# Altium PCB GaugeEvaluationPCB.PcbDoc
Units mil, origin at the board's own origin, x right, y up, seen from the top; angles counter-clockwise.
Board outline 3520.03 x 1613.16 mil, 2 copper layers (Top Layer, Bottom Layer), stack 62 mil thick; 46 components, 37 nets, 143 pads, 56 vias.
Unrouted connection lines stored in the file: 25.
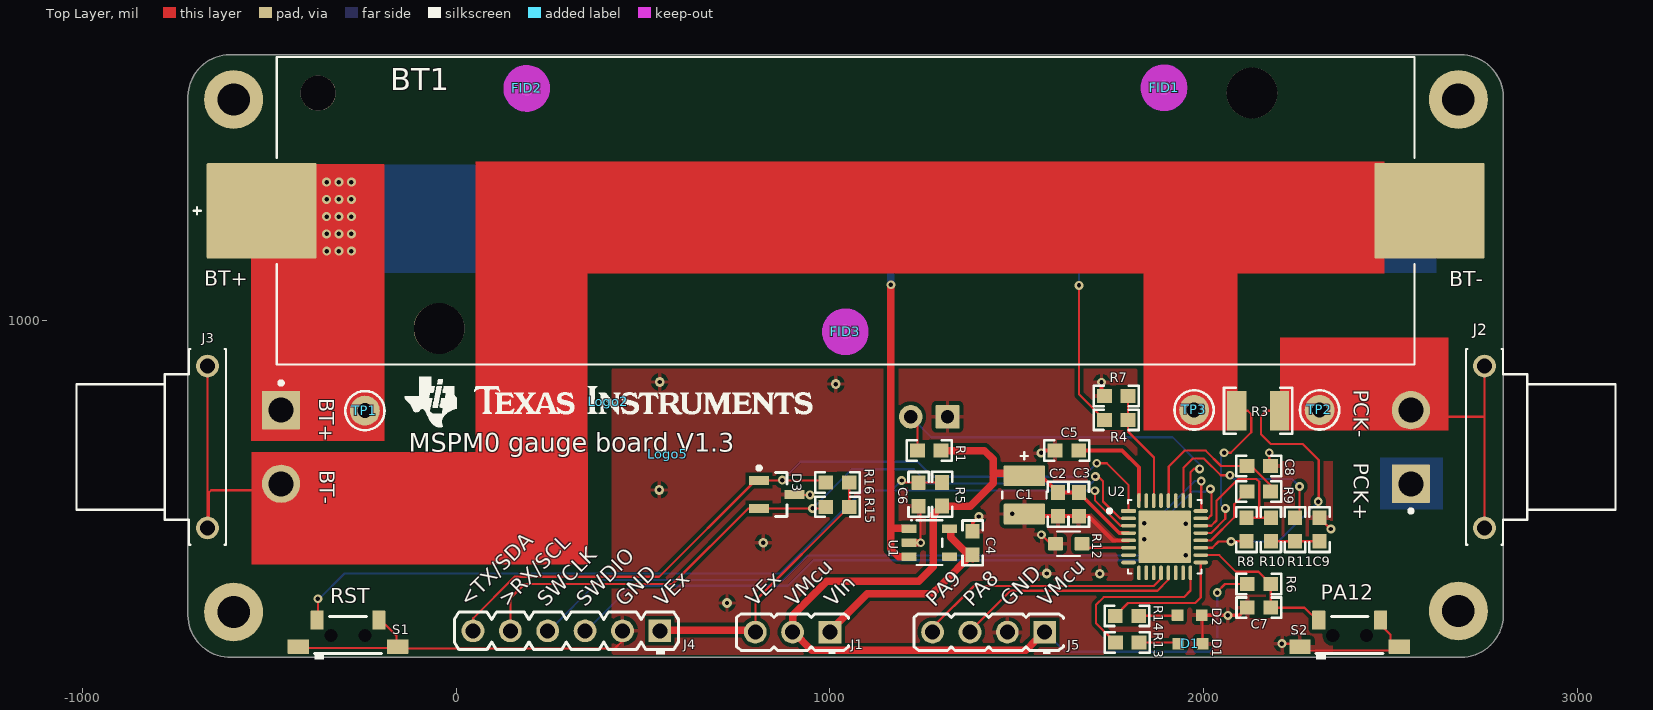
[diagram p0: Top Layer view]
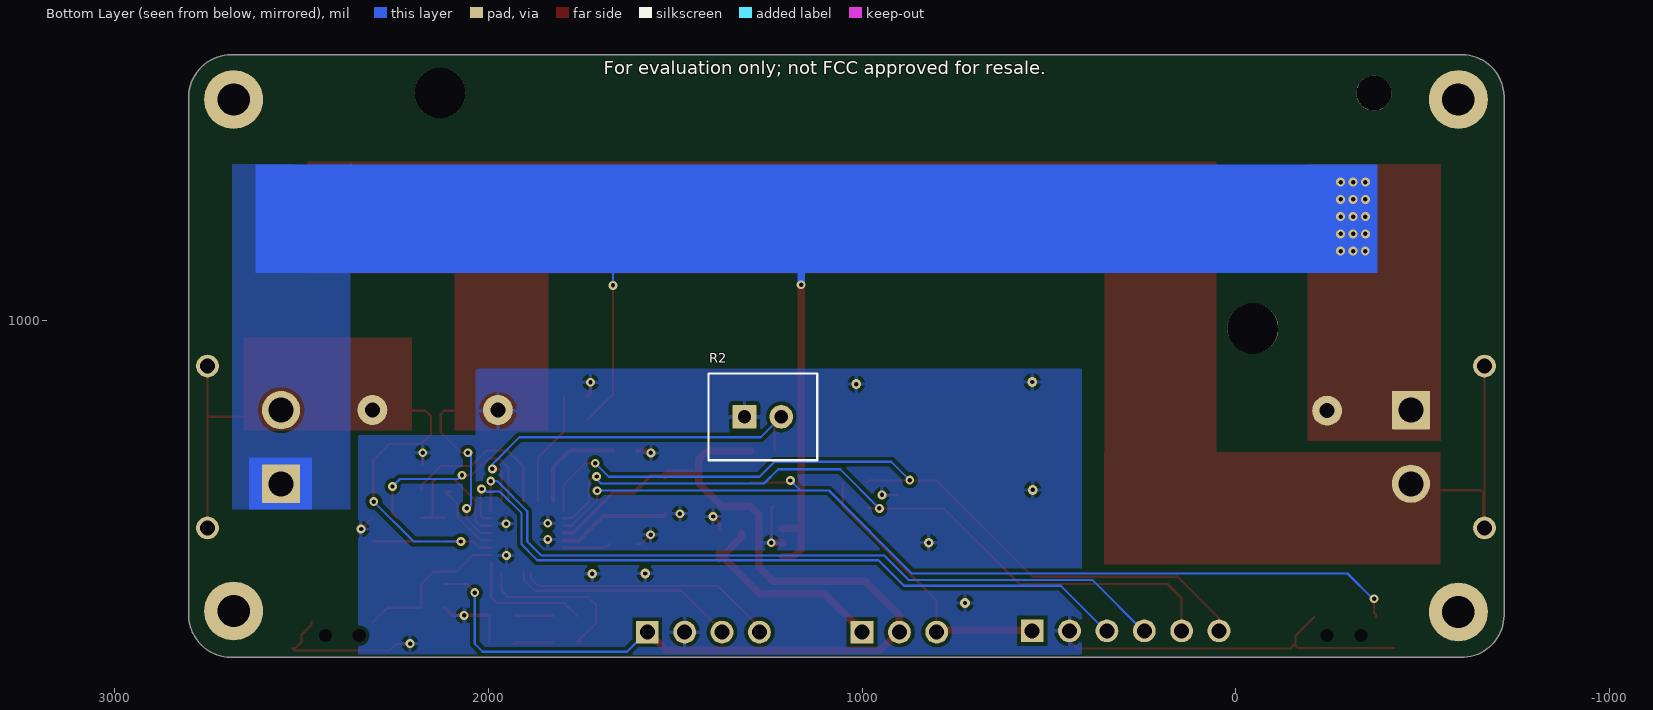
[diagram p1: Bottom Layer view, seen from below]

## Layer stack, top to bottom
Top Solder: solder mask 0.4, Solder Resist, Dk 3.5
Top Layer: signal copper 1.4
Dielectric1: core 59.2, FR-4, Dk 4.8
Bottom Layer: signal copper 1.4
Bottom Solder: solder mask 0.4, Solder Resist, Dk 3.5

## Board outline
-601.61,99.61 cw(c-603.45,213.91) -717.76,212.44 cw(c-712.75,212.5) -717.77,212.5 -717.77,1599.75 cw(c-712.75,1599.75) -717.63,1600.9 cw(c-603.34,1598.45) -604.81,1712.76 cw(c-604.75,1707.75) -602.57,1712.26 2686.19,1712.26 cw(c2686.19,1707.25) 2687.23,1712.16 cw(c2687.95,1597.84) 2802.26,1599.31 cw(c2797.25,1599.25) 2802.27,1599.25 cw(c2797.25,1599.25) 2802.26,1599.22 2802.27,212.25 cw(c2797.25,212.25) 2802.12,211.05 cw(c2687.84,214.05) 2689.31,99.74 cw(c2689.25,104.75) 2689.25,99.73 -600.56,99.73 cw(c-601.69,104.62)

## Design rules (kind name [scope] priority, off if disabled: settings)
AcuteAngle [All] p1: minimum=4.50000000000000E+0001 checktracksonly=FALSE
AssemblyTestPointUsage [All] p1: valid=2
BoardOutlineClearance BoardOutlineClearance_MountingHoles [OnCopper and InComponentClass('Mounting Holes')] p1: gap=6 ignorepadtopadclearanceinfootprint=FALSE
BoardOutlineClearance BoardOutlineClearance_Poly [OnCopper and IsPoly] p2: gap=6 ignorepadtopadclearanceinfootprint=FALSE
BoardOutlineClearance [OnCopper and Not InComponentClass('Logo') and not InComponentClass('FiducialMark') and not InRegion(1000,500,4000,800) and not InPoly] p3: gap=6 ignorepadtopadclearanceinfootprint=FALSE
Clearance Clearance_Keepouts [((IsTrack Or IsArc) And Not InPoly) And IsFree and IsKeepOut vs ((IsTrack Or IsArc) And Not InPoly) And IsFree and IsKeepOut] p1: gap=10 ignorepadtopadclearanceinfootprint=FALSE
Clearance Clearance_Poly [InPolygon] p2: gap=10 ignorepadtopadclearanceinfootprint=TRUE
Clearance Clearance_FiducialMark [IsKeepOut and InComponentClass('FiducialMark') vs IsPad and InComponentClass('FiducialMark')] p3: gap=10 ignorepadtopadclearanceinfootprint=FALSE
Clearance [All] p4: gap=6 ignorepadtopadclearanceinfootprint=TRUE
ComponentClearance ComponentClearance_MountingHoles_FiducialMarks [InComponentClass('Mounting Holes') vs InComponentClass('FiducialMark')] p1: gap=0 collisioncheckmode=3 verticalgap=10 showdistances=FALSE
ComponentClearance ComponentClearance_Shunt [InComponentClass('Header') vs InComponentClass('Shunt')] p2: gap=0 collisioncheckmode=3 verticalgap=0 showdistances=FALSE
ComponentClearance ComponentClearance_Logo [InComponentClass('Logo')] p3: gap=0 collisioncheckmode=3 verticalgap=10 showdistances=FALSE
ComponentClearance ComponentClearance_ScrewToNut [(HasFootprint('NY PMS 440 0025 PH')) vs (HasFootprint('Keystone_1902C'))] p4: gap=0 collisioncheckmode=3 verticalgap=10 showdistances=FALSE
ComponentClearance ComponentClearance_MountingHoles [InComponentClass('Mounting Holes')] p5: gap=0 collisioncheckmode=3 verticalgap=100000 showdistances=FALSE
ComponentClearance ComponentClearance_SmallPassives [HasFootprint('0201*') or HasFootprint('0402*') or HasFootprint('0508') or HasFootprint('0603*') or HasFootprint('0612') or HasFootprint('0805*') or HasFootprint('0815*') or HasFootprint('0830*') or HasFootprint('1206*') or HasFootprint('1210*') or HasFootprint('1808*') or HasFootprint('1812*') or HasFootprint('1825*') or HasFootprint('2010*') or HasFootprint('2220*') or HasFootprint('2225*') or HasFootprint('2512*') or HasFootprint('2728*') or HasFootprint('3518*') vs HasFootprint('0201*') or HasFootprint('0402*') or HasFootprint('0508') or HasFootprint('0603*') or HasFootprint('0612') or HasFootprint('0805*') or HasFootprint('0815*') or HasFootprint('0830*') or HasFootprint('1206*') or HasFootprint('1210*') or HasFootprint('1808*') or HasFootprint('1812*') or HasFootprint('1825*') or HasFootprint('2010*') or HasFootprint('2220*') or HasFootprint('2225*') or HasFootprint('2512*') or HasFootprint('2728*') or HasFootprint('3518*')] p6: gap=0 collisioncheckmode=3 verticalgap=10 showdistances=FALSE
ComponentClearance ComponentClearance_THtoSMT [IsThruComponent vs IsSMTComponent] p7: gap=0 collisioncheckmode=3 verticalgap=30 showdistances=FALSE
ComponentClearance ComponentClearance_THtoTH [IsThruComponent vs IsThruComponent] p8: gap=0 collisioncheckmode=3 verticalgap=30 showdistances=FALSE
ComponentClearance [All] p9: gap=0 collisioncheckmode=3 verticalgap=10 showdistances=FALSE
DiffPairsRouting [All] p1: maxlimit=100 minlimit=10 mostfreqgap=10 toplayer_minwidth=15 toplayer_maxwidth=15 toplayer_prefwidth=15 bottomlayer_minwidth=15 bottomlayer_maxwidth=15 bottomlayer_prefwidth=15 maxuncoupledlength=1000
FabricationTestPointUsage TestPointUsage [All] p1: valid=2 allowmultiple=FALSE
FabricationTestpoint Testpoint [All] p1: side=3 testpointundercomponent=TRUE minsize=40 maxsize=100 preferedsize=60 minholesize=0 maxholesize=40 preferedholesize=32 testpointgrid=1 allowsidetop=TRUE allowsidebottom=TRUE usegrid=TRUE gridtolerance=0.01
FanoutControl Fanout_LCC [IsLCC] p1: bgadir=Out bgaviamode=Centered fanoutstyle=Auto fanoutdirection=Alternating viagrid=1 // Fanout_LCC (Default Rule)
FanoutControl Fanout_BGA [IsBGA] p2: bgadir=Out bgaviamode=Centered fanoutstyle=Auto fanoutdirection=Alternating viagrid=1 // Fanout_BGA (Default Rule)
FanoutControl Fanout_Default [All] p4: bgadir=Out bgaviamode=Centered fanoutstyle=Auto fanoutdirection=Alternating viagrid=1 // Fanout_Default (Default Rule)
FanoutControl Fanout_Small [(CompPinCount < 5)] p5: bgadir=Out bgaviamode=Centered fanoutstyle=Auto fanoutdirection=OutThenIn viagrid=1 // Fanout_Small (Default Rule)
Height [All] p1: minheight=0 maxheight=99999 prefheight=500
HoleSize [All] p1: absolutevalues=TRUE maxlimit=251 minlimit=7.87 maxpercent=80.000 minpercent=20.000
MinimumAnnularRing MinimumAnnularRing_ThermalPadVias [IsVia and InAnyComponent] p1: minimumring=5.91
MinimumAnnularRing [All] p2: minimumring=5.91
MinimumSolderMaskSliver MinimumSolderMaskSliver_Logo [InComponentClass('Logo') vs InComponentClass('Logo')] p1: minsoldermaskwidth=0.7
MinimumSolderMaskSliver [All] p2: minsoldermaskwidth=0
PlaneConnect [All] p1: planeconnectstyle=Relief reliefexpansion=10 reliefentries=4 reliefconductorwidth=10 reliefairgap=10
PolygonConnect [All] p1: connectstyle=Relief reliefconductorwidth=10 reliefentries=4 polygonreliefangle="90 Angle" airgapwidth=10
RoutingVias ThermalPadVias [IsVia and InAnyComponent] p1: holewidth=11.81 width=23.62 viastyle="Through Hole" minholewidth=7.87 minwidth=19.68 maxholewidth=17.72 maxwidth=35.43
RoutingVias [All] p2: holewidth=11.81 width=23.62 viastyle="Through Hole" minholewidth=7.87 minwidth=23.62 maxholewidth=40 maxwidth=65
SilkToBoardRegionClearance [Not ((IsComment or IsDesignator) And (Hide <> 'False')) and not InRegion(1000,500,4000,800)] p1:
SilkToSilkClearance SilkToSilkClearance_Pb-FreeLogo [(HasFootprint('Pb-Free_Overlay_Medium') OR HasFootprint('Pb-Free_Overlay_Small')) vs (HasFootprint('Pb-Free_Overlay_Medium') OR HasFootprint('Pb-Free_Overlay_Small'))] p1: silktosilkclearance=0
SilkToSilkClearance [All] p2: silktosilkclearance=0
SilkToSolderMaskClearance SilkToComponentPadClearance [(IsPad or IsFill or IsRegion) and InAnycomponent] p1: minsilkscreentomaskgap=0 clearancetoexposedcopper=TRUE
SilkToSolderMaskClearance "Silk to Solder Mask Opening" [All] p2: minsilkscreentomaskgap=0 clearancetoexposedcopper=FALSE
SolderMaskExpansion [All] p1: expansion=1.97 istentingtop=FALSE
UnRoutedNet [All] p1: checkbadconnections=TRUE
Width [All] p1: maxlimit=100 minlimit=6 preferedwidth=6 checkconnectedcopper=TRUE
13 further rules are at their usual default settings.

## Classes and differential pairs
component class Logo: Logo2
component class FiducialMark: FID1 FID2 FID3
component class Header: J1 J4 J5

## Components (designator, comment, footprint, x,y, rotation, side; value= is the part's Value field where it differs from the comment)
BT1 "1042P" FP-1042P_BT_HOLDER-MFG 1042.25,1294.75 r180 top
C1 "TAJB475K010RNJ" FP-TAJB475K010RNJ_1210-MFG 1520.5,534.5 r90 top
C2 "GRM188R61A106KAALD" 0603 1610.5,509.25 r90 top value=10uF
C3 "C0603X104K3RACTU" 0603 1666.25,509.25 r270 top value=0.1uF
C4 "C1608X5R1A105K080AC" 0603 1382.25,406 r90 top value=1uF
C5 "C0603C474K8PACTU" 0603 1634.25,653.5 r180 top value=0.47uF
C6 "C0603X104K3RACTU" 0603 1237.73,535.88 r270 top value=0.1uF
C7 "C0603X104K3RACTU" 0603 2148.25,232.75 r180 top value=0.1uF
C8 "C0603X104K3RACTU" 0603 2147.75,611.75 r0 top value=0.1uF
C9 "C0603X104K3RACTU" 0603 2310,441.75 r90 top value=0.1uF
D1 "SML-D12U1WT86" LED_SMLD12_RED 1964.98,136.03 r0 top value=Red
D2 "SML-D12U1WT86" LED_SMLD12_RED 1963,212.78 r0 top value=Green
D3 "BAT64-06" INF-SOT23_M 858,535.75 r0 top
FID1 "Fiducial" Fiducial10-30 1894.25,1623.75 r0 top
FID2 "Fiducial" Fiducial10-30 189.03,1622.25 r90 top
FID3 "Fiducial" Fiducial10-30 1041.5,971 r90 top
J1 "22284033" Molex_0022284033 900.5,167.25 r180 top
J2 "XT30PW-F" FP-XT30PW-F_CONN_SOCKET_DC2-MFG 2902.34,662.71 r270 top
J3 "XT30PW-F" FP-XT30PW-F_CONN_SOCKET_DC2-MFG -815.75,662.71 r90 top
J4 "PBC06SAAN" Sullins_PxC06SAAN 295.16,170.75 r180 top
J5 "22284043" Molex_0022284043 1425,167.25 r180 top
Logo2 "Texas Instruments" TI_Horizontal_Overlay_Small 407.66,784.12 r0 top
Logo5 "FCC disclaimer" FCC_disclaimer 566.5,643.25 r0 top
R1 "RNCF0603TKY10K0" 0603 1266.25,653.25 r0 top value=10.0k
R2 "NTCALUG01A103F161L" FP-NTCALUG01A103F161L_PTH_7MM2_5MM6-MFG 1265.79,743.5 r180 bottom value=10k
R3 "ERJ-L14KF20MU" 1210 2146.09,760 r180 top value=0.02
R4 "RG1608P-223-B-T5" 0603 1766.25,735.54 r180 top value=220.0k
R5 "RT0603BRD0747KL" 0603 1300.48,536.13 r270 top value=47.0k
R6 "RT0603BRD0747KL" 0603 2148.25,296 r180 top value=47.0k
R7 "RG1608P-104-B-T5" 0603 1766.25,799.18 r0 top value=100.0k
R8 "ERJ3EKF1602V" 0603 2115,441.75 r270 top value=16.0k
R9 "RG1608P-162-B-T5" 0603 2147.75,543.5 r0 top value=1.60k
R10 "RC0603FR-07115KL" 0603 2180.04,441.75 r90 top value=110k
R11 "RG1608P-162-B-T5" 0603 2245.02,441.75 r90 top value=1.60k
R12 "RN73C1J100KBTG" FP-RN73C1J100KBTG_0603-MFG 1639.25,403.75 r180 top value=100k
R13 "RC0603FR-071KL" 0603 1796,139.28 r0 top value=1.00k
R14 "RC0603FR-071KL" 0603 1795.25,211.03 r0 top value=1.00k
R15 "RC0603FR-072K2L" 0603 1020.59,502.75 r0 top value=2.20k
R16 "RC0603FR-072K2L" 0603 1020.59,567.5 r0 top value=2.20k
S1 "1188E-1K2-V-TR" SW_1188E -289.25,171.75 r90 top
S2 "1188E-1K2-V-TR" SW_1188E 2391.03,171.75 r90 top
TP1 "5117" Keystone5117 -243.97,759.88 r90 top
TP2 "5117" Keystone5117 2310.5,761.75 r90 top
TP3 "5117" Keystone5117 1974.75,761.75 r90 top
U1 "TLV70018DDCR" DDC0005A_N 1266.12,406.6 r0 top
U2 "MSPM0L1306TRHB" RHB0032E-IPC_A 1896.03,422.58 r0 top

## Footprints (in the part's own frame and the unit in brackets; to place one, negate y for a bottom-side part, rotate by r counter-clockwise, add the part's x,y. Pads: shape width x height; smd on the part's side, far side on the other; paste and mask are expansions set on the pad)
0603 [mm] "0603 from SM-752 data"
  rect 1x0.95 smd: 1(-0.8,0) 2(0.8,0)
  silkscreen extent -1.52,-0.69 1.52,0.69, body extent -0.87,-0.47 0.87,0.47, height 1
1210 [mm] "1210 from SM-752 data"
  rect 1.3x2.7 smd: 1(-1.45,0) 2(1.45,0)
  silkscreen extent -2.32,-1.57 2.32,1.57, body extent -1.7,-1.35 1.7,1.35, height 1.35
DDC0005A_N [mm]
  rrect17% 1x0.6 smd: 1(-1.375,0.95) 2(-1.375,0) 3(-1.375,-0.95) 4(1.375,-0.95) 5(1.375,0.95)
  silkscreen extent -1.25,-1.52 0.88,1.57, body extent -1.41,-1.45 1.41,1.45, height 1.1
FCC_disclaimer [mil]
Fiducial10-30 [mm]
  round 1 smd mask+1: 1(0,0)
  Top Layer keep-out circle w1.678: c0,0 r0.75
FP-1042P_BT_HOLDER-MFG [mil]
  rrect2% 294x255 smd paste+0 mask+0: 1(-1562.5,0) 2(1562.5,0)
  round 135.83 hole 135.83 unplated paste-39370.1 mask+0: ""(-1087.5,-315) ""(1087.5,315)
  round 94 hole 94 unplated paste-39370.1 mask+0: ""(1411.5,-315)
  silkscreen extent -1522,-412 1745,412, body extent -1713,-415 1713,415, height 10
FP-NTCALUG01A103F161L_PTH_7MM2_5MM6-MFG [mm]
  rrect6% 1.61x1.61 hole 0.91 paste-1000 mask+0: 1(-1.25,0)
  round 1.61 hole 0.91 paste-1000 mask+0: 2(1.25,0)
  silkscreen extent -3.7,-2.95 3.7,2.95, body extent -3.6,-2.82 3.6,2.8, height 54
FP-RN73C1J100KBTG_0603-MFG [mm]
  rrect11% 1x0.9 smd paste+0 mask+0: 1(-0.9,0) 2(0.9,0)
  silkscreen extent -0.77,-0.82 0.78,0.83, body extent -0.77,-0.4 0.78,0.4, height 0.55
FP-TAJB475K010RNJ_1210-MFG [mm]
  rrect7% 1.4x2.8 smd paste+0 mask+0: 1(-1.3,0) 2(1.3,0)
  silkscreen extent -0.23,-1.5 2.9,1.5, body extent -2.1,-1.6 2.1,1.6, height 0.25
FP-XT30PW-F_CONN_SOCKET_DC2-MFG [mm]
  rrect4% 2.6x2.6 hole 1.7 paste-1000 mask+0: 1(2.5,-8.825)
  round 2.6 hole 1.7 paste-1000 mask+0: 2(-2.5,-8.825)
  round 1.55 hole 1 paste-1000 mask+0: 3(-5.5,-3.825) 4(5.5,-3.825)
  silkscreen extent -6.65,-8.95 6.65,5.07, body extent -6.75,-10.23 6.75,5.18, height 0.25
INF-SOT23_M [mm] "SOT23, 3-Leads, Body 2.9x1.3 mm, Pitch 0.95 mm, IPC Low Density"
  rect 1.35x0.6 smd: 1(-1.2,0.95) 2(-1.2,-0.95) 3(1.2,0)
  silkscreen extent -1.32,-1.5 0.7,1.92, body extent -0.7,-1.5 0.7,1.5, height 1.1
Keystone5117 [mil] "For Keystone 500x miniature loop terminals"
  round 80 hole 40: 1(0,0)
  silkscreen extent -52,-52 52,52, body extent -49,-49 49,49, height 182
LED_SMLD12_RED [mm] "SMD, 2-Leads, Body 1.6x0.8mm"
  rrect12% 0.8x0.8 smd: 1(-0.825,0) 2(0.825,0)
  body extent -0.8,-0.4 0.8,0.4, height 0.55
Molex_0022284033 [mm] "Header, 2.54mm, 3x1, TH"
  rect 1.55x1.55 hole 1.02: 1(-2.54,0)
  round 1.55 hole 1.02: 2(0,0) 3(2.54,0)
  silkscreen extent -3.81,-1.24 3.81,1.5, body extent -3.81,-1.24 3.81,1.24, height 8.4
Molex_0022284043 [mm] "Header, 2.54mm, 4x1, TH"
  rect 1.55x1.55 hole 1.02: 1(-3.81,0)
  round 1.55 hole 1.02: 2(-1.27,0) 3(1.27,0) 4(3.81,0)
  silkscreen extent -5.08,-1.24 5.08,1.5, body extent -5.08,-1.24 5.08,1.24, height 8.4
RHB0032E-IPC_A [mm]
  rrect41% 1.01x0.242 smd paste+0 mask+0: 1(-2.451,1.75)
  rrect100% 1.01x0.242 smd paste+0 mask+0: 2(-2.451,1.25) 3(-2.451,0.75) 4(-2.451,0.25) 5(-2.451,-0.25) 6(-2.451,-0.75) 7(-2.451,-1.25) 8(-2.451,-1.75) 17(2.451,-1.75) 18(2.451,-1.25) 19(2.451,-0.75) 20(2.451,-0.25) 21(2.451,0.25) 22(2.451,0.75) 23(2.451,1.25) 24(2.451,1.75)
  rrect100% 0.242x1.01 smd paste+0 mask+0: 9(-1.75,-2.451) 10(-1.25,-2.451) 11(-0.75,-2.451) 12(-0.25,-2.451) 13(0.25,-2.451) 14(0.75,-2.451) 15(1.25,-2.451) 16(1.75,-2.451) 25(1.75,2.451) 26(1.25,2.451) 27(0.75,2.451) 28(0.25,2.451) 29(-0.25,2.451) 30(-0.75,2.451) 31(-1.25,2.451) 32(-1.75,2.451)
  rrect3% 3.55x3.55 smd paste-1000 mask+0: 33(0,0)
  silkscreen extent -3.88,-2.5 2.5,2.5, body extent -3.46,-3.46 3.46,3.46, height 0.25
Sullins_PxC06SAAN [mm] "Header, 2.54mm, 6x1, TH"
  rect 1.55x1.55 hole 1.016: 1(-6.35,0)
  round 1.55 hole 1.016: 2(-3.81,0) 3(-1.27,0) 4(1.27,0) 5(3.81,0) 6(6.35,0)
  silkscreen extent -7.62,-1.27 7.62,1.6, body extent -7.62,-1.27 7.62,1.27, height 8.38
SW_1188E [mm] "SMD, 4-Leads, Body 7.8x3.5mm"
  rrect10% 1x1.45 smd: 1(-1.1,3.375) 2(-1.1,-3.375)
  rrect11% 1.3x0.9 smd: 3(0.7,2.1) 4(0.7,-2.1)
  round 0 hole 0.9 unplated: ""(-0.35,1.15) ""(-0.35,-1.15)
  silkscreen extent -1.97,-2.28 0.95,2.28, body extent -2.55,-3.9 1.05,3.9, height 3.5
TI_Horizontal_Overlay_Small [mil]
  silkscreen extent -545,-68 545,67

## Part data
BT1: library part CMP-0092114-1, "Battery Holder (Open) 18650 1 Cell SMD (SMT) Tab", Digikey Part Number=36-1042P-ND, Manufacturer=Keystone, Mouser Part Number=534-1042P, Operating Temperature Range="-50°C to +145°C"
C1: library part CMP-0089269-1, "220µF Molded Tantalum Capacitors 10V 1411 (3528 Metric), 1210 4Ohm", Digikey Part Number=478-3886-1-ND, Manufacturer="AVX Corporation", Mouser Part Number=581-TAJB475K010R, Operating Temperature Range="-55°C to +125°C", Tolerance_%=10%, ValueDisplayed=220uF
C2: library part CMP-0086193-1, "CAP, CERM, 10 µF, 10 V,+/- 10%, X5R, 0603", Cap_Case=0603, Manufacturer=MuRata, TempCo=X5R, Tolerance_%=10%, Value2=10V, ValueDisplayed=10µF
C3 C6 C7 C8 C9: library part CMP-0006979-3, "CAP, CERM, 0.1 uF, 25 V, +/- 10%, X7R, 0603", Cap_Case=0603, Manufacturer=Kemet, Supplier Part Number 1=399-5345-1-ND, TempCo=X7R, Tolerance_%=10%, Value1=Unknown, Value2=25V, ValueDisplayed=0.1uF
C4: library part CMP-0007002-5, "CAP, CERM, 1 uF, 10 V, +/- 10%, X5R, 0603", Cap_Case=0603, Manufacturer=TDK, Supplier Part Number 1=445-1321-1-ND, TempCo=X5R, Tolerance_%=10%, Value1=Unknown, Value2=10V, ValueDisplayed=1uF
C5: library part CMP-0006945-1, "CAP, CERM, 0.47 uF, 10 V, +/- 10%, X5R, 0603", Cap_Case=0603, Manufacturer=Kemet, Supplier Part Number 1=399-3114-1-ND, TempCo=X5R, Tolerance_%=10%, Value1=Unknown, Value2=10V, ValueDisplayed=0.47uF
D1 D2: library part CMP-0086209-1, "LED, Red, SMD", Color=Red, Manufacturer=Rohm, Power_TotalModule=54mW, Value1=0.054W, Value2=2.2V
D3: library part CMP-1182-00011-1, "Silicon Schottky Diode, SOT23, Reel, Green", Manufacturer=Infineon
FID1 FID2 FID3: library part CMP-0077181-1, "Fiducial mark.  There is nothing to buy or mount.", Manufacturer=N/A
J1: library part CMP-0055332-1, "Header, 2.54mm, 3x1, Tin, TH", Color=Black, Current_A=4A, Manufacturer=Molex, Supplier Part Number 1=WM50016-03-ND, Voltage_V=250V
J2 J3: library part CMP-0035193-1, "Socket, DC supply, XT30, female, PIN: 2, on PCBs, THT, yellow, 15A", Current_A=15A, Manufacturer=Amass, Operating Temperature Range="-20°C to +120°C", Voltage_V=500V
J4: library part CMP-0054603-1, "Header, 2.54mm, 6x1, Gold, TH", Color=Black, Current_A=3A, Manufacturer="Sullins Connector Solutions", Supplier Part Number 1=S1011E-06-ND
J5: library part CMP-0055331-1, "Header, 2.54mm, 4x1, Tin, TH", Color=Black, Current_A=4A, Manufacturer=Molex, Supplier Part Number 1=WM50016-04-ND, Voltage_V=250V
Logo2: library part CMP-0074838-1, "Texas Instrument Corporate Signature"
Logo5: library part CMP-0074847-1, "FCC_disclaimer"
R1: library part CMP-0023626-3, "RES, 10.0 k, 1%, 0.063 W, 0603", Manufacturer="Stackpole Electronics Inc", Power_W=63mW, Supplier Part Number 1=RNCF0603TKY10K0CT-ND, TempCo="5 ppm/C", Tolerance_%=1%, Value1=0.01%, Value2=0.063W, Value_Code=10k0
R2: library part CMP-0091769-1, "NTC Thermistors; NTC Lug 10k 1% 3435K awg#24 PTFE 600V 16", B Tolerance=1%, Digikey Part Number=BC2896-ND, Manufacturer=Vishay, Mouser Part Number=594-NTLUG01A103F161L, Operating Temperature Range="-40°C to +150°C"
R3: library part CMP-0015069-2, "RES, 0.02, 1%, 0.33 W, 1210", Manufacturer=Panasonic, Power_W=330mW, Supplier Part Number 1=P20NACT-ND, TempCo="300 ppm/C", Tolerance_%=1%, Value2=0.33W, Value_Code=R020, ValueDisplayed=0.02
R4: library part CMP-0023474-2, "RES, 220.0 k, 0.1%, 0.1 W, 0603", Manufacturer="Susumu Co Ltd", PartNumber=RG1608P-224-B-T5, Power_W=100mW, Supplier Part Number 1=RG16P220.0KBCT-ND, TempCo="25 ppm/C", Tolerance_%=0.1%, Value2=0.1W, Value_Code=220k0, ValueDisplayed=220.0k
R5: library part CMP-0024267-2, "RES, 47.0 k, 1%, 0.1 W, 0603", Manufacturer="Yageo America", Power_W=100mW, TempCo="25 ppm/C", Tolerance_%=1%, Value1=0.1%, Value2=0.1W, Value_Code=47k0, ValueDisplayed=47.0k
R6: library part CMP-0024267-2, "RES, 47.0 k, 1%, 0.1 W, 0603", Manufacturer="Yageo America", Power_W=100mW, TempCo="25 ppm/C", Tolerance_%=0.1%, Value1=1%, Value2=0.1W, Value_Code=47k0, ValueDisplayed=47.0k
R7: library part CMP-0023404-1, "RES, 100.0 k, 0.1%, 0.1 W, 0603", Manufacturer="Susumu Co Ltd", Power_W=100mW, Supplier Part Number 1=RG16P10.0KBCT-ND, TempCo="25 ppm/C", Tolerance_%=0.1%, Value2=0.1W, Value_Code=100k0, ValueDisplayed=100.0k
R8: library part CMP-0078661-1, "RES, 16.0 k, 1%, 0.1 W, AEC-Q200 Grade 0, 0603", Manufacturer=Panasonic, Power_W=100mW, Supplier Part Number 1=P16.0KHCT-ND, TempCo="100 ppm/C", Tolerance_%=1%, Value2=0.1W, Value_Code=16k0, ValueDisplayed=16.0k
R9 R11: library part CMP-0023448-3, "RES, 1.60 k, 0.1%, 0.1 W, 0603", Manufacturer="Susumu Co Ltd", Power_W=100mW, Supplier Part Number 1=RG16P1.6KBCT-ND, TempCo="25 ppm/C", Tolerance_%=0.1%, Value2=0.1W, Value_Code=1k60, ValueDisplayed=1.60k
R10: library part CMP-0022756-4, "RES, 110 k, 1%, 0.1 W, 0603", Manufacturer=Yageo, Power_W=100mW, Supplier Part Number 1=311-110KHRCT-ND, TempCo="100 ppm/C", Tolerance_%=1%, Value2=0.1W, Value_Code=110k
R12: library part CMP-0093027-1, "Thin Film Resistors RN 0603 100KΩ 0.1% 10ppm/°C", Manufacturer="TE Connectivity", Operating Temperature Range="-55°C to +155°C", Power_W=63mW, TempCo=10ppm/°C, Tolerance_%=0.1%
R13 R14: library part CMP-0022895-5, "RES, 1.00 k, 1%, 0.1 W, 0603", Manufacturer=Yageo, Power_W=100mW, Supplier Part Number 1=311-1.00KHRCT-ND, TempCo="100 ppm/C", Tolerance_%=1%, Value2=0.1W, Value_Code=1k00, ValueDisplayed=1.00k
R15 R16: library part CMP-0022986-5, "RES, 2.20 k, 1%, 0.1 W, 0603", Manufacturer=Yageo, Power_W=100mW, Supplier Part Number 1=311-2.20KHRCT-ND, TempCo="100 ppm/C", Tolerance_%=1%, Value2=0.1W, Value_Code=2k20, ValueDisplayed=2.20k
S1 S2: library part CMP-0002328-1, "Switch, SPST, 0.05 A, 12 VDC, SMD", CurrentRating_mA=50A, Manufacturer=Diptronics
TP1 TP2 TP3: library part CMP-0055154-1, "Test Point, Miniature, Blue, TH", Color=Blue, Manufacturer=Keystone, Supplier Part Number 1=36-5117-ND
U1: library part CMP-0035825-1, "Single Output LDO, 200 mA, Fixed 1.8 V Output, 2 to 5.5 V Input, with Low IQ, 5-pin SOT (DDC), -40 to 125 degC, Green (RoHS & no Sb/Br)", Manufacturer="Texas Instruments"
U2: library part CMP-0092679-1, "Mixed-Signal Microcontroller VQFN32", Frequency_Fixed=32MHz, Manufacturer="Texas Instruments", Max Supply Voltage=3.6V, Min Supply Voltage=1.62V, Operating Temperature Range="-40°C to +105°C"

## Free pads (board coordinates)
  round 157.48 hole 86.61: 3(-595.25,1592.5) 4(2682,1592.5) 5(-595.25,221.25) 6(2682,223.75)

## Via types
v1: diameter 23.62, hole 11.81, Top Layer to Bottom Layer, 49 vias
v2: diameter 25.98, hole 11.81, Top Layer to Bottom Layer, 7 vias

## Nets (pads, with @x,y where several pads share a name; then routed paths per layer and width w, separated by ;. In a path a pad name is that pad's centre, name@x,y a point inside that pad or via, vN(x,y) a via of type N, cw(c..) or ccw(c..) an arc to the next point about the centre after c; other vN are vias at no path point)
1V8: C4.1 J1.1 U1.5 | length 560.3
  Top Layer w20: J1.1@1001.37,171.25 1100.37,270.25 1274.5,270.25 1297.5,293.25 C4.1@1382.5,378.25 ; U1.5@1323.88,432.4 1323.88,421.62 1374.87,370.63 1382,363.5 C4.1@1382.5,363.5
A1: R4.1 R7.2 U2.30 | length 309.4
  Top Layer w6: R7.2 R4.1 1797.75,704 1867.47,634.28 1867.47,520.06 U2.30
A5: R1.1 R2.2 U2.25 | length 1039.7
  Top Layer w6: R2.2 1234.75,725.32 R1.1 ; U2.25 1964.93,594.93 1974.25,604.25 v1(1989.5,604.25)
  Bottom Layer w6: R2.2 1271.57,688.5 1917.25,688.5 1976.5,629.25 1989.5,616.25 v1(1989.5,604.25)
A9: J2.2 J2.3 J2.4 R3.1 R8.2 TP2.1 U2.19 | length 1436.2
  Top Layer w6: U2.19 2023.31,393.06 2040,409.75 v1(2073.75,409.75) v1@2073.75,419 ; v1@2082.49,410.26 R8.2 ; R3.1 2168.5,760 2153.5,745 2153.5,696.5 2179.5,670.5 2265.25,670.5 2308,627.75 2308,517.75 v1(2306.75,516.5) ; J2.2@2554.81,743.93 2751.66,743.93 ; J2.4@2751.66,428.96 2751.66,743.93 ; J2.3@2751.66,862.04 2751.66,743.93
  Bottom Layer w6: v1(2073.75,409.75) 2200,409.75 v1(2306.75,516.5)
ADCIN_A3: C8.1 R9.2 U2.28 | length 432
  Top Layer w6: U2.28 1906.84,520.06 1906.84,610.75 1949.09,653 2005.75,653 2047,611.75 C8.1 2128,611.75 2179.25,560.5 R9.2@2179.25,548.76
BAT+: BT1.2 J2.1 J3.1 R4.2 TP1.1 U1.1 U1.3 | length 1365.9
  Top Layer w6: v1(1666.75,1095) 1666.75,803.54 R4.2
  Top Layer w20: v1(1163.5,1096.75) 1163.5,445 ; U1.3 1183.8,369.2 1163.5,389.5 1163.5,445 ; U1.1 1210.98,445 1163.5,445
  Bottom Layer w6: v1(1666.75,1095) 1666.75,1174.75 1667.75,1175.75
  Bottom Layer w10: 1161.5,1180 1163.5,1178 1163.5,1145.5
  Bottom Layer w20: v1(1163.5,1096.75) 1163.5,1145.5
  other v1: -346.22,1186.88 -313.72,1186.88 -280.22,1186.88 -346.47,1233.01 -313.72,1233.01 -280.22,1233.01 -346.47,1279.13 -313.72,1279.13 -280.22,1279.13 -346.47,1325.26 -313.72,1325.26 -280.22,1325.26 -346.47,1371.38 -313.72,1371.38 -280.22,1371.38
BAT-: BT1.1 C1.1 C2.1 C3.2 C4.2 C5.2 C6.2 C7.2 C8.2 C9.2 D1.2 D2.2 D3.3 J3.2 J3.3 J3.4 J4.2 J5.2 R2.1 R3.2 R7.1 R12.2 S1.1 S1.2 S1.4 S2.1 S2.2 S2.4 TP3.1 U1.2 U2.5 U2.21 U2.33 | length 4865.3
  Top Layer w6: J3.4@-665.16,862.04 -665.16,428.96 -661,433.12 -661,541.5 -655.43,547.07 J3.2@-468.31,547.07 ; S1.1@-422.12,125.19 -165.63,125.19 S1.2@-156.79,134.04 ; S1.4@-209.7,207.62 -159.5,157.42 -159.5,136.75 S1.2@-156.79,134.04 ; J4.2@445.75,168.5 445.75,144.25 424.75,123.25 -146,123.25 S1.2@-156.79,134.04 ; D3.3 906.49,534.5 v1(947,534.5) ; C6.2 1242.9,499.22 v1@1242.9,406.6 ; v1(1566.25,428) 1590.5,403.75 R12.2 ; U2.21 2020.43,432.43 2058.4,470.4 v1(2058.4,498.35) ; D2.2 1997.46,210.79 D1.2 ; v1(2055.1,647.1) 2072.6,647.1 2127.5,702 2127.5,750.5 2118,760 R3.2 1975,760 1974.75,759.75 1974.75,1313.75 2584,1313.75 BT1.1@2604.75,1293 ; v1(2175.75,647.25) 2175.75,615.25 C8.2 ; v1(2209.79,136.47) 2210.23,136.03 2246.1,136.03 2258.15,123.97 2263.87,118.25 2518.18,118.25 2523.9,123.97 2517.01,123.97 2500.32,140.66 2500.32,160.34 2473.7,186.96 S2.4@2473.7,194.84 ; C9.2 2340,443.25 v1(2340.75,443.25)
  Top Layer w10: C4.2@1382.5,441.25 1382.5,460.25 v1(1399,476.75) ; C1.1@1526.5,483.15 1531.89,477.75 C2.1 C3.2 1692.5,477.75 1757.51,412.74 U2.5 ; v1(1565.25,646.75) 1572,653.5 C5.2 ; v1(1727,836) 1727,806.94 R7.1 ; D2.2 2096.78,212.78 C7.2
  Top Layer w20: U1.2 v1@1242.9,406.6
  Bottom Layer w6: v1(2055.1,647.1) 2047,639 2047,507.75 2053.25,501.5 2054.25,502.5 v1(2058.4,498.35) ; v1@2172.5,644 v1(2175.75,647.25)
  other v1: 2065,212 1952,372.5 1243.25,406.25 1841.5,415.5 1952.75,457.25 1841.5,458.5 1487.75,484.25
  other v2: 724.99,245.32 1722,323.2 1580.74,324.14 822.12,406.59 543.61,547.89 1015.85,831 544.7,836.58
Key: C7.1 R6.1 S2.3 U2.18 | length 426.8
  Top Layer w6: U2.18 2041.88,373.37 2086.5,328.75 2147,328.75 R6.1 C7.1 2270.44,232.75 S2.3@2308.35,194.84
LED_1: R13.1 U2.16 | length 448.7
  Top Layer w6: R13.1@1754.22,139.28 R13.1 1712.5,191.28 1712.5,240.25 1733.25,261 1947.5,261 1964.93,278.43 U2.16
LED_2: R14.1 U2.17 | length 342.9
  Top Layer w6: R14.1 1797.98,245.25 1978,245.25 1992.53,259.78 U2.17
NetC9_1: C9.1 R10.1 R11.1 | length 130
  Top Layer w6: R10.1 R11.1 C9.1
NetD1_1: D1.1 R13.2 | length 106.4
  Top Layer w6: R13.2 1929.26,139.28 D1.1
NetD2_1: D2.1 R14.2 | length 104.5
  Top Layer w6: R14.2 1928.77,211.03 D2.1
OPA_IN+_A7: R8.1 R10.2 U2.22 | length 403.2
  Top Layer w6: U2.22 2020.61,452.11 2034.5,466 2034.5,518.75 2092.75,577 2141.25,577 2148.75,569.5 2148.75,473.25 ; R8.1 2148.75,473.25 ; R10.2 2148.75,473.25
OPA_OUT_A8: R9.1 U2.20 | length 215
  Top Layer w6: U2.20 2020.24,412.74 2082.26,474.76 2082.26,509.51 R9.1 R9.1@2099.5,543.5
PA.0: D3.1 J4.6 R16.1 U2.1 | length 2213
  Top Layer w6: J4.6@45.75,168.5 45.75,204.75 156.25,315.25 543.25,315.25 801.15,573.15 D3.1 983.44,573.15 R16.1 ; v1(1714.25,619.25) 1740.75,619.25 1799.52,560.48 U2.1
  Bottom Layer w6: v1(872.5,574) 922,623.5 1234.75,623.5 1275,583.25 1678.25,583.25 v1(1714.25,619.25) v1@1718.5,623.5
PA.1: D3.2 J4.5 R15.1 U2.2 | length 2040.7
  Top Layer w6: J4.5@145.75,168.5 145.75,258.86 182.89,296 579.25,296 781.6,498.35 D3.2 v1(954,498.35) 984.69,498.35 R15.1 ; v1@1714.38,574.38 1710.5,578.27 v1(1710.5,583.75) 1718.5,583.75 1731,571.25 1731,517 1776.2,471.8 U2.2
  Bottom Layer w6: v1(954,498.35) 1058.65,603 1224.5,603 1262.75,564.75 1698.82,564.75 1700.63,566.56 ; 1700.68,566.56 1710.5,576.38 v1(1710.5,583.75)
PA.2: R12.1 U2.6 | length 129.3
  Top Layer w6: R12.1 1685.38,393.06 U2.6
PA.3: U2.7
PA.4: U2.8
PA.5: U2.9
PA.6: U2.10
PA.7: U2.11
PA.8: J5.4 U2.12 | length 691.6
  Top Layer w6: J5.4@1275,169.5 1275,180.38 1385.62,291 1866.75,291 1886.19,310.44 U2.12
PA.9: J5.3 U2.13 | length 606.7
  Top Layer w6: J5.3@1375,169.5 1483.5,278 1876.5,278 1905.87,307.37 U2.13
PA.10: U2.14
PA.11: U2.15
PA.19: J4.3 U2.23 | length 1983.1
  Top Layer w6: U2.23 2012.41,471.8 2021.41,480.79 2021.41,547.09 v1(2018.25,550.25)
  Bottom Layer w6: J4.3@345.75,168.5 468.5,291.25 888,291.25 956.5,359.75 1869.5,359.75 1911.25,401.5 1911.25,485.1 1969.51,543.36 1987.96,543.36 1988.13,543.19 2005.37,543.19 2012.43,550.25 v1(2018.25,550.25)
PA.20: J4.4 U2.24 | length 2045.4
  Top Layer w6: U2.24 1996.75,495.7 1993.75,498.7 v1(1993.75,571.5)
  Bottom Layer w6: J4.4@245.75,168.5 384.38,307.12 875.88,307.12 941.25,372.5 1858.75,372.5 1896.03,409.78 1896.03,490.78 1969.25,564 1976.75,571.5 v1(1993.75,571.5)
PA.22: R11.2 U2.26 | length 529
  Top Layer w6: U2.26 1946.21,520.06 1946.21,607.15 1971.06,632 2000.75,632 2045.75,587 v1(2070.75,587) ; R11.2 2256.75,484.98 v1(2256.75,557)
  Bottom Layer w6: v1(2070.75,587) 2080.75,577 2236.75,577 v1(2256.75,557)
PA.23: U2.29
PA.25: U2.27
PA.27: U2.31
R\S\T\: C6.1 R5.1 S1.3 U2.3 | length 2541.5
  Top Layer w6: S1.3@-375.05,207.62 -375.05,213.95 -369.75,219.25 v1(-369.75,256.75) ; v1(1192,573) 1197.62,567.38 C6.1 1300.23,567.38 R5.1 ; v1(1709.25,545.75) 1709.25,520.5 1777.64,452.11 U2.3
  Bottom Layer w6: v1(-369.75,256.75) -366.5,256.75 -298.75,324.5 867.21,324.5 1088.96,546.25 1168.5,546.25 ; v1(1192,573) 1168.5,549.5 1168.5,546.25 ; v1@1709.25,546.25 1168.5,546.25
VCC_ext: J1.3 J4.1 R15.2 R16.2 | length 759.5
  Top Layer w6: J1.3@799.87,172.75 801.37,171.25 801.37,252.04 R15.2 R16.2
  Top Layer w20: J4.1@545.75,168.5 J4.1@549.25,165 ; J4.1@547.5,172.75 J1.3@799.87,172.75
VCC_MCU: C1.2 C2.2 C3.1 J1.2 J5.1 R1.2 R5.2 R6.2 U2.4 | length 2888.6
  Top Layer w6: v1(2036.5,273) 2036.5,275.25 2057.25,296 R6.2
  Top Layer w10: C1.2@1526.5,585.51 1565.74,585.51 C2.2 C3.1 1774.57,432.43 U2.4
  Top Layer w20: R1.2 1413.5,653.25 1436.93,629.82 1436.93,595.07 ; C1.2@1526.5,585.51 1519.51,592.5 1439.5,592.5 1436.93,595.07 ; J5.1@1575,169.5 J5.1 1554.49,146.74 1552.24,146.74 1523.75,118.25 951.75,118.25 900.5,169.5 900.5,212.66 991.59,303.75 1238,303.75 1276.75,342.5 1276.75,480.9 R5.2 1375.39,504.64 1436.93,566.18 1436.93,595.07
  Bottom Layer w6: J5.1@1575,169.5 1629.5,115 2015.25,115 2036.5,136.25 v1(2036.5,273)
VCORE: C5.1 U2.32 | length 269.3
  Top Layer w10: C5.1 1781.88,653.5 1827.13,608.25 U2.32
pads on no net: BT1. FID1.1 FID2.1 FID3.1 S1. S2. U1.4

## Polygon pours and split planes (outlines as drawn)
BAT- on Bottom Layer "Bottom Layer-BAT-" (solid, pour order 34): 412.5,871.75 412.5,101.25 2348,108.25 2348,691.5 2345.25,694.25 2033.75,694.25 2033.75,871.75 2034.5,872.5
BAT+ on Bottom Layer "Bottom Layer-BAT+" (solid, pour order 32): 2361.25,1418.25 2370,1409.5 2370,495.5 2686.19,495.5 2686.19,1420.08
BAT- on Top Layer "TOP_LAYER_BAT-_P035" (solid, remove dead copper, pour order 35): 412.5,871.75 416.04,868.22 416.04,106.18 2334.44,106.18 2345.25,95.37 2345.25,624.77 1822.62,624.77 1822.62,869.39 1820.26,871.75

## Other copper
Top Layer:
  rectangle net A9: 2205.07,706.75 2655.25,955.5
  rectangle net BAT-: -547.25,348.75 353,648.75
  region net BAT+: -191.5,678.35 -191.5,1419.5 -548.25,1419.5 -548.25,678.35
  region net BAT-: 52.17,1426.08 52.17,458.33 352.17,458.33 352.17,1426.08
  region net BAT-: 2484.5,1426.75 95,1426.75 95,1126.75 2484.5,1126.75
  region net BAT-: 2090.25,706.75 2090.25,1205.25 1840,1205.25 1840,706.75
Bottom Layer:
  rectangle net BAT+: 2472.68,495.95 2641,633.95
  rectangle net BAT+: -379,1128 2622.75,1419
  pour cut-out: 2044.25,657.84 2044.25,498.35 2068.25,498.35 2068.25,657.84

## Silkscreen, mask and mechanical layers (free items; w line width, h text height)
Top Overlay:
  text "BT+" at -674,1094 h40
  text "BT-" at 2658,1092.75 h40
  text "PCK-" at 2402.5,815.45 h40 r270
  text "BT+" at -366.5,793.69 h40 r270
  text "MSPM0 gauge board V1.3" at -127.25,650.25 h50
  text "PCK+" at 2402.5,620 h40 r270
  text "BT-" at -365,600 h40 r270
  text "PA12" at 2313.5,254.5 h40
  text "RST" at -336.75,245 h40
  text "<TX/SDA" at 32.5,232.82 h40 r45
  text ">RX/SCL" at 136.86,232.82 h40 r45
  text "SWCLK" at 241.21,232.82 h40 r45
  text "SWDIO" at 345.57,232.82 h40 r45
  text "GND" at 449.92,232.82 h40 r45
  text "VEx" at 554.28,232.82 h40 r45
  text "VEx" at 799.37,232.82 h40 r45
  text "VMcu" at 904.25,232.82 h40 r45
  text "VIn" at 1009.12,232.82 h40 r45
  text "PA9" at 1281.42,232.82 h40 r45
  text "PA8" at 1381.03,232.82 h40 r45
  text "GND" at 1480.64,232.82 h40 r45
  text "VMcu" at 1580.25,232.82 h40 r45
M1 Board Outline:
  lines w10: -712.75,1599.75 -712.75,212.5 ccw(c-603.45,213.91) -601.69,104.62 ; -712.63,1596.69 cw(c-603.34,1598.45) -604.75,1707.75 ; -605.25,1707.25 2686.19,1707.25 ; -605,104.75 2689.25,104.75 ccw(c2687.84,214.05) 2797.13,215.81 ; 2686.19,1707.13 cw(c2687.95,1597.84) 2797.25,1599.25 2797.25,215.81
